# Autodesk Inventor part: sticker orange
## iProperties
Shininess: 64.0
Length Units: 11269
Angle Units: 11279
Time Units: 11290
Mass Units: 11283
Length Display Precision: 3
Angle Display Precision: 2
Compacted: True
Part Number: sticker orange
Document SubType Name: Modeling
Created: 2004-10
Material: Standard
Designer: W. Holzwarth
Manufacturer: Standard
Standards Organization: Custom
Density: 0.0
Volumn: 0.0
Area: 0.0
PropertySet Name: Model Information
Control State: 0
Master: False
Checked Out: False
Author: W. Holzwarth
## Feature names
1. Basis1
